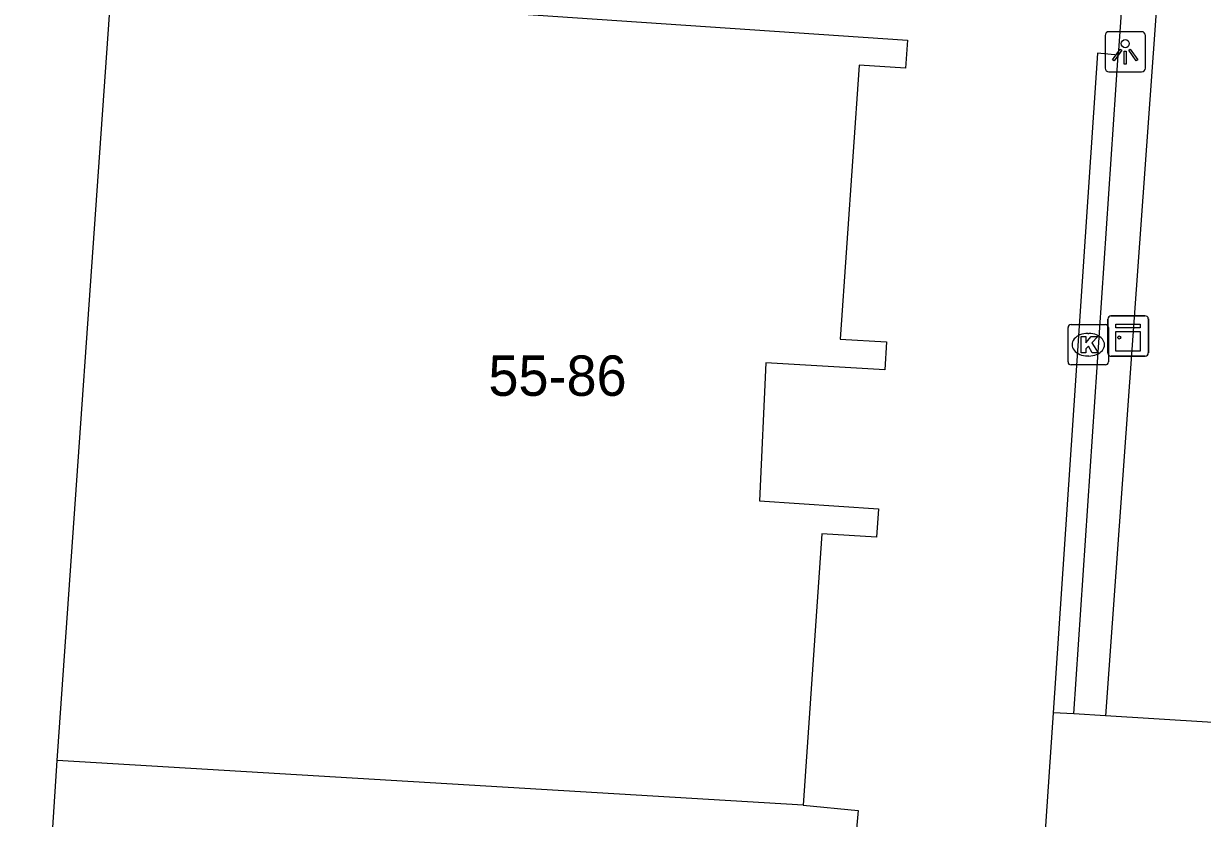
# Model space of a CAD drawing. Extents: x 161848 to 162726, y 385382 to 386521.
# Drawn here: x 162109.71 to 162138.88, y 385651.84 to 385671.53 of the extents above; entities that cross this region are included whole.
import ezdxf

# ---------------------------------------------------------------- set-up
doc = ezdxf.new("R2010")
doc.units = 0
for name, color, linetype in [('IMGEO_Haag', 7, 'Continuous'), ('IMGEO_Kast', 7, 'Continuous'), ('IMGEO_Kolk', 7, 'Continuous'), ('IMGEO_Lichtpunt', 7, 'Continuous'), ('IMGEO_Pand', 7, 'Continuous'), ('IMGEO_Pand_nummerreeks', 7, 'Continuous'), ('IMGEO_Voetpad_open', 7, 'Continuous')]:
    doc.layers.add(name, color=color, linetype=linetype)

msp = doc.modelspace()

# ---------------------------------------------------------------- linework, layer by layer
at = {"layer": 'IMGEO_Haag'}
msp.add_lwpolyline([(162129.353, 385681.999), (162138.422, 385681.358), (162136.486, 385654.387)], dxfattribs=at)
at = {"layer": 'IMGEO_Kast'}
for p, q in [((162136.545, 385663.364), (162136.545, 385664.205)), ((162136.545, 385664.205), (162136.545, 385663.364)), ((162136.62, 385664.289), (162137.461, 385664.289)), ((162137.461, 385664.289), (162136.62, 385664.289)), ((162137.545, 385664.214), (162137.545, 385663.373)), ((162137.545, 385663.373), (162137.545, 385664.214)), ((162137.47, 385663.289), (162136.629, 385663.289)), ((162136.629, 385663.289), (162137.47, 385663.289))]:
    msp.add_line(p, q, dxfattribs=at)
for points in [[(162136.74, 385664.079), (162137.34, 385664.079), (162137.34, 385663.994), (162136.74, 385663.994), (162136.74, 385664.079)], [(162136.74, 385663.904), (162137.34, 385663.904), (162137.34, 385663.415), (162136.74, 385663.415), (162136.74, 385663.904)]]:
    msp.add_lwpolyline(points, dxfattribs=at)
msp.add_circle((162136.824, 385663.753), 0.0377, dxfattribs=at)
for centre, start, end in [((162136.623, 385664.211), 92.4484, 184.2845), ((162136.623, 385664.211), 92.4484, 184.2845), ((162137.467, 385664.211), 2.4484, 94.2845), ((162137.467, 385664.211), 2.4484, 94.2845), ((162136.623, 385663.367), 182.4484, 274.2845), ((162136.623, 385663.367), 182.4484, 274.2845), ((162137.467, 385663.367), 272.4484, 4.2845), ((162137.467, 385663.367), 272.4484, 4.2845)]:
    msp.add_arc(centre, 0.0779, start, end, dxfattribs=at)
at = {"layer": 'IMGEO_Kolk'}
for p, q in [((162135.558, 385663.148), (162135.558, 385664)), ((162135.633, 385664.074), (162136.485, 385664.074)), ((162136.046, 385663.854), (162136.071, 385663.854)), ((162136.559, 385664), (162136.559, 385663.148)), ((162136.069, 385663.294), (162136.044, 385663.294)), ((162136.485, 385663.074), (162135.633, 385663.074))]:
    msp.add_line(p, q, dxfattribs=at)
for points in [[(162135.558, 385663.148), (162135.558, 385664)], [(162135.633, 385664.074), (162136.485, 385664.074)], [(162136.559, 385664), (162136.559, 385663.148)], [(162135.879, 385663.774), (162136.002, 385663.774), (162136.002, 385663.623), (162136.132, 385663.774), (162136.296, 385663.774), (162136.15, 385663.623), (162136.303, 385663.374), (162136.151, 385663.374), (162136.066, 385663.538), (162136.002, 385663.471), (162136.002, 385663.374), (162135.879, 385663.374), (162135.879, 385663.774)], [(162136.485, 385663.074), (162135.633, 385663.074)]]:
    msp.add_lwpolyline(points, dxfattribs=at)
for centre, start, end in [((162135.635, 385663.998), 91.552, 178.448), ((162135.635, 385663.998), 91.552, 178.448), ((162136.483, 385663.998), 1.552, 88.448), ((162136.483, 385663.998), 1.552, 88.448), ((162135.635, 385663.15), 181.552, 268.448), ((162135.635, 385663.15), 181.552, 268.448), ((162136.483, 385663.15), 271.552, 358.448), ((162136.483, 385663.15), 271.552, 358.448)]:
    msp.add_arc(centre, 0.0765, start, end, dxfattribs=at)
for centre, major_axis, ratio, start_param, end_param in [((162136.045, 385663.574), (-0.387, 0.002), 0.722429, 4.712389, 7.853982), ((162136.07, 385663.574), (-0.39, 0.002), 0.717154, 1.570796, 4.712389)]:
    msp.add_ellipse(centre, major_axis=major_axis, ratio=ratio, start_param=start_param, end_param=end_param, dxfattribs=at)
at = {"layer": 'IMGEO_Lichtpunt'}
for p, q in [((162136.475, 385671.231), (162136.475, 385670.424)), ((162136.475, 385671.231), (162136.475, 385670.424)), ((162137.377, 385671.326), (162136.569, 385671.326)), ((162137.377, 385671.326), (162136.569, 385671.326)), ((162137.471, 385670.424), (162137.471, 385671.231)), ((162137.471, 385670.424), (162137.471, 385671.231)), ((162136.569, 385670.33), (162137.377, 385670.33)), ((162136.569, 385670.33), (162137.377, 385670.33))]:
    msp.add_line(p, q, dxfattribs=at)
for points in [[(162136.849, 385670.895), (162136.888, 385670.867), (162136.7, 385670.605), (162136.662, 385670.632), (162136.849, 385670.895)], [(162136.951, 385670.847), (162136.998, 385670.847), (162136.998, 385670.525), (162136.951, 385670.525), (162136.951, 385670.847)], [(162137.061, 385670.867), (162137.099, 385670.894), (162137.286, 385670.632), (162137.247, 385670.604), (162137.061, 385670.867)]]:
    msp.add_lwpolyline(points, dxfattribs=at)
msp.add_circle((162136.974, 385671.029), 0.0994, dxfattribs=at)
for centre, start, end in [((162136.569, 385671.231), 90, 180), ((162136.569, 385671.231), 90, 180), ((162137.377, 385671.231), 0, 90), ((162137.377, 385671.231), 0, 90), ((162136.569, 385670.424), 180, 270), ((162136.569, 385670.424), 180, 270), ((162137.377, 385670.424), 270, 0), ((162137.377, 385670.424), 270, 360)]:
    msp.add_arc(centre, 0.0946, start, end, dxfattribs=at)
at = {"layer": 'IMGEO_Pand'}
for points in [[(162110.547, 385653.275), (162111.889, 385672.456)], [(162111.889, 385672.456), (162114.644, 385672.269), (162131.582, 385671.118), (162131.538, 385670.424), (162130.39, 385670.497), (162129.921, 385663.713), (162131.069, 385663.643), (162131.027, 385662.949), (162128.082, 385663.127), (162127.921, 385659.704), (162130.865, 385659.507), (162130.818, 385658.804), (162129.463, 385658.887), (162129.006, 385652.172)], [(162109.714, 385640.396), (162110.547, 385653.275)], [(162129.006, 385652.172), (162110.547, 385653.275)], [(162129.006, 385652.172), (162130.369, 385652.042), (162130.3, 385651.31), (162128.962, 385651.395), (162128.146, 385639.456), (162129.511, 385639.343), (162129.484, 385639.013)]]:
    msp.add_lwpolyline(points, dxfattribs=at)
at = {"layer": 'IMGEO_Voetpad_open'}
for points in [[(162129.312, 385681.4), (162129.335, 385681.254), (162137.502, 385680.681), (162136.8, 385670.741)], [(162136.8, 385670.741), (162136.284, 385670.795), (162135.192, 385654.46)], [(162135.701, 385654.436), (162136.8, 385670.741)], [(162135.192, 385654.46), (162134.982, 385651.414)], [(162135.701, 385654.436), (162135.192, 385654.46)], [(162136.486, 385654.387), (162135.701, 385654.436)], [(162153.353, 385653.333), (162136.486, 385654.387)]]:
    msp.add_lwpolyline(points, dxfattribs=at)

# ---------------------------------------------------------------- texts
at = {"layer": 'IMGEO_Pand_nummerreeks'}
msp.add_text('55-86', height=1, dxfattribs=at).set_placement((162121.216, 385662.308))

doc.saveas('drawing.dxf')
